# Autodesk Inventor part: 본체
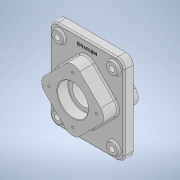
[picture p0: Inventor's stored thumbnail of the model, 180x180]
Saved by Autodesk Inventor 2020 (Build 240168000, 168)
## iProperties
Created: 2021-07
Part Number: 본체
Material: 일반
Document SubType Name: Modeling
Designer: Owner
Density: 1 g/cm^3
Appearance: 기본값
Mass: 807.977 g
Surface Area: 961.758 cm^2
Volume: 807.977 cm^3
Author: Owner
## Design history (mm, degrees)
sketch "스케치1"
  geometry: L1 (-75, -90)-(75, -90); L2 (75, -90)-(75, 90); L3 (75, 90)-(-75, 90); L4 (-75, 90)-(-75, -90); L5 (-75, -90)-(75, 90); L6 (75, -90)-(-75, 90); 1 further point
  constraints: 12 end point, 2 midpoint, 2 parallel, 1 horizontal, 1 perpendicular
  dimensions: "d0" = 150 distance of L2.end L3.end; "d1" = 180 distance of L1.end L2.end
extrude "돌출1" new body sketch "스케치1" stored distance "d2" = 18; taper "d3" = 0 deg
fillet "모깎기1" dims "d4" = 15
fillet "모깎기2" dims "d5" = 3
sketch "스케치2"
  geometry: C1 r 11 at (-55, 70); 1 further point
  constraints: 1 centre point
  dimensions: "d6" = 70 vertical distance of point (0, 0) C1.centre; "d7" = 55 horizontal distance of point (0, 0) C1.centre; "d8" = 22 diameter of C1
extrude "돌출2" join sketch "스케치2" distance "d9" = 5; taper "d10" = 0 deg
sketch "스케치3"
  geometry: C1 r 11 at (0, 0) reference; 2 further points
  constraints: 1 coincident
hole "구멍1" sketch "스케치3" at (0, 0) diameter "d11" = 11; stored, may be unused: countersink angle "d15" = 90 deg, drill point angle "d17" = 118 deg; dims "d12" = 6, "d13" = 4, "d14" = 2, "d16" = 8
sketch "스케치4"
  geometry: L1 (0, -70.711)-(70.711, 0); L2 (70.711, 0)-(0, 70.711); L3 (0, 70.711)-(-70.711, 0); L4 (-70.711, 0)-(0, -70.711); L5 (0, -70.711)-(0, 70.711); L6 (70.711, 0)-(-70.711, 0); 1 further point
  constraints: 12 end point, 2 midpoint, 2 parallel, 1 horizontal, 1 perpendicular, 1 vertical
  dimensions: "d18" = 100 distance of L1.end L2.end
extrude "돌출3" join sketch "스케치4" distance "d19" = 29; taper "d20" = 0 deg
sketch "스케치5"
  geometry: L1 (0, 70.711)-(70.711, 0) reference; L2 (70.711, 0)-(0, -70.711) reference; L3 (70.711, 0)-(0, -70.711) reference; L4 (0, -70.711)-(-70.711, 0) reference; L5 (-70.711, 0)-(0, 70.711) reference; L6 (0, 70.711)-(70.711, 0) reference; 3 further points
extrude "돌출4" join sketch "스케치5" distance "d21" = 23; taper "d22" = 0 deg
fillet "모깎기3" dims "d23" = 20
fillet "모깎기4" dims "d24" = 20
fillet "모깎기5" dims "d25" = 3
fillet "모깎기6" dims "d26" = 3
fillet "모깎기7" dims "d27" = 3
sketch "스케치7"
  geometry: 2 further points
  constraints: 1 vertical alignment
  dimensions: "d28" = 48 distance of point (0, 0) point (0, 48)
hole "구멍2" sketch "스케치7" at (0, 48) diameter "d29" = 4.917; stored, may be unused: countersink angle "d33" = 90 deg, drill point angle "d35" = 118 deg; dims "d30" = 10, "d31" = 4, "d32" = 2, "d34" = 13
sketch "스케치8"
  geometry: 2 further points
  constraints: 1 coincident
hole "구멍3" sketch "스케치8" at (0, 0) diameter "d36" = 45; stored, may be unused: countersink angle "d40" = 90 deg, drill point angle "d42" = 118 deg; dims "d37" = 10, "d38" = 62, "d39" = 22, "d41" = 13
sketch "스케치9"
  geometry: 2 further points
  constraints: 1 coincident
hole "구멍4" sketch "스케치9" at (0, 0) diameter "d43" = 45; stored, may be unused: countersink angle "d47" = 90 deg, drill point angle "d49" = 118 deg; dims "d44" = 10, "d45" = 62, "d46" = 22, "d48" = 13
chamfer "모따기1" distance "d50" = 1; stored, may be unused: second distance "d51" = 2, angle "d52" = 45 deg
fillet "모깎기8" dims "d53" = 1
sketch "스케치10"
  geometry: 2 further points
  constraints: 1 vertical alignment
  dimensions: "d57" = 48 distance of point (0, 0) point (0, 48)
hole "구멍5" sketch "스케치10" at (0, 48) diameter "d58" = 4.917; stored, may be unused: countersink angle "d62" = 90 deg, drill point angle "d64" = 118 deg; dims "d59" = 10, "d60" = 62, "d61" = 22, "d63" = 13
sketch "스케치11"
  geometry: L1 (60, 90)-(-60, 90) reference; 2 further points
  constraints: 1 vertical alignment, 1 other
  dimensions: "d68" = 15 distance from line of point (0, 75) L1
feature "엠보싱1" sketch "스케치11" dims "d0" = 150, "d1" = 180, "d69" = 0.5, "d70" = 0
node "솔리드1"
mirror "미러1"
mirror "미러2"
pattern_circular "원형 패턴1" dims angle "d55" = 360 deg
pattern_circular "원형 패턴2" dims angle "d66" = 360 deg
node "투영된 루프1"
feature "A9D066F2-1C7D-4E18-AEED-F7BC21143FA4" dims "d11" = 11, "d12" = 6, "d13" = 4, "d14" = 2, "d15" = 90 deg, "d16" = 8, "d17" = 118 deg
